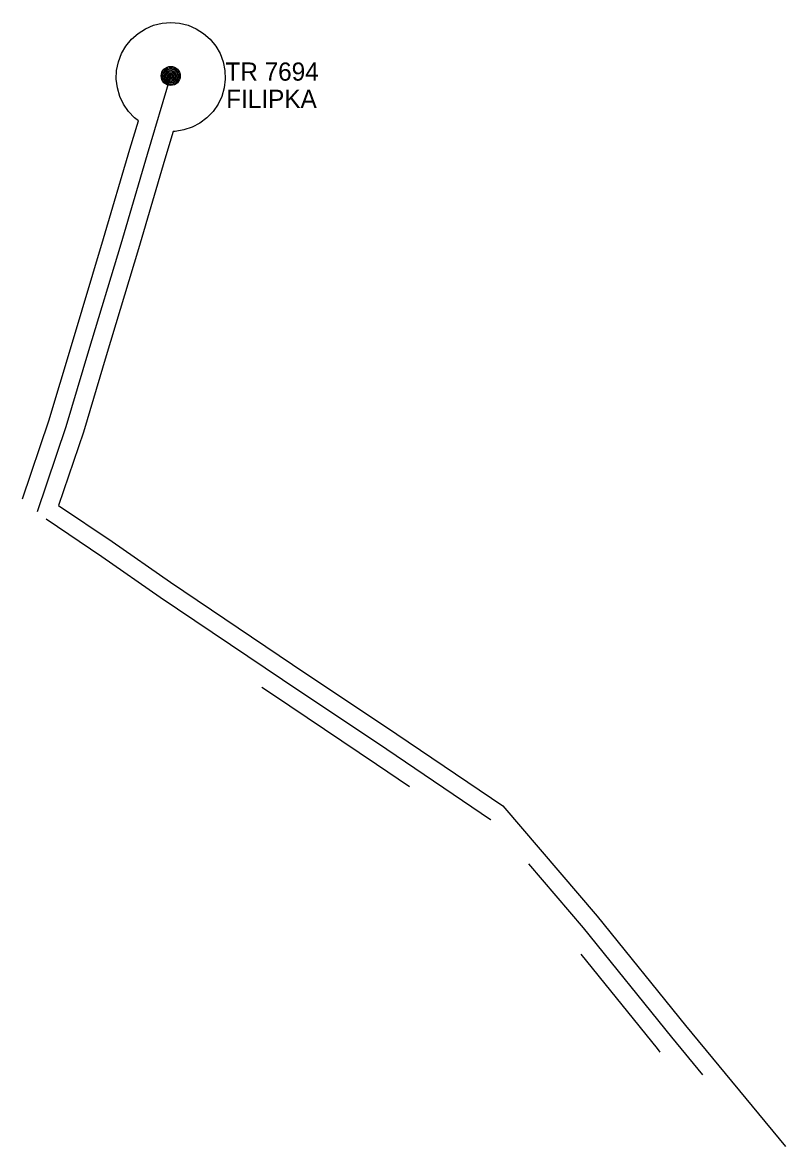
# Model space of a CAD drawing. Extents: x -439095 to -431527, y -1129525 to -1119219.
# Drawn here: x -436127 to -435708, y -1129525 to -1128907 of the extents above; entities that cross this region are included whole.
import ezdxf

# ---------------------------------------------------------------- set-up
doc = ezdxf.new("R2010")
doc.units = 0
for name, color, linetype in [('13861012_venkovní vedení elektrické sítě VN 1-35 kV_Stav', 7, 'Continuous'), ('14801013_OP vedení elektrické sítě_Stav', 7, 'Continuous'), ('Trafostanice', 7, 'Continuous'), ('Vrstva 13', 7, 'Continuous')]:
    doc.layers.add(name, color=color, linetype=linetype)

msp = doc.modelspace()

# ---------------------------------------------------------------- linework, layer by layer
at = {"layer": '13861012_venkovní vedení elektrické sítě VN 1-35 kV_Stav'}
for points in [[(-436118.97, -1129175.73), (-436103.05, -1129129.02), (-436090.64, -1129087.28), (-436072.97, -1129028.48), (-436058.42, -1128979.12), (-436058.42, -1128979.12), (-436045.78, -1128936.61), (-436045.65, -1128936.11)], [(-436114.14, -1129179.87), (-436083.54, -1129200.57), (-436083.54, -1129200.57), (-436051.43, -1129222.83), (-435984.18, -1129268.23), (-435926.85, -1129306.63), (-435869.79, -1129345.24), (-435869.65, -1129345.4)], [(-435848.84, -1129369.7), (-435818.82, -1129404.77), (-435770.25, -1129464.95), (-435753.15, -1129485.66)]]:
    msp.add_lwpolyline(points, dxfattribs=at)
at = {"layer": '14801013_OP vedení elektrické sítě_Stav'}
for points in [[(-436063.39, -1128960.75), (-436065.49, -1128959.18), (-436068.83, -1128955.7), (-436071.58, -1128951.72), (-436073.64, -1128947.36), (-436074.99, -1128942.72), (-436075.57, -1128937.93), (-436075.38, -1128933.11), (-436074.41, -1128928.38), (-436072.7, -1128923.86), (-436070.28, -1128919.68), (-436067.23, -1128915.94), (-436063.62, -1128912.74), (-436059.54, -1128910.16), (-436055.09, -1128908.27), (-436050.41, -1128907.11), (-436045.59, -1128906.72), (-436040.78, -1128907.11), (-436036.09, -1128908.27), (-436031.65, -1128910.16), (-436027.57, -1128912.74), (-436023.96, -1128915.94), (-436020.9, -1128919.68), (-436018.49, -1128923.86), (-436016.78, -1128928.38), (-436015.81, -1128933.11), (-436015.62, -1128937.93), (-436016.2, -1128942.72), (-436017.54, -1128947.36), (-436019.61, -1128951.72), (-436022.36, -1128955.7), (-436025.7, -1128959.18), (-436029.56, -1128962.08), (-436033.84, -1128964.32), (-436038.41, -1128965.85), (-436043.18, -1128966.63), (-436044.27, -1128966.63)], [(-436127.15, -1129168.73), (-436112.58, -1129125.98), (-436100.22, -1129084.42), (-436082.55, -1129025.63), (-436068.07, -1128976.49), (-436068.07, -1128976.48), (-436063.39, -1128960.75)], [(-436044.27, -1128966.63), (-436048.8, -1128981.85), (-436063.38, -1129031.33), (-436081.06, -1129090.14), (-436093.52, -1129132.06), (-436107.28, -1129172.44), (-436077.87, -1129192.33), (-436077.82, -1129192.37), (-436045.78, -1129214.57), (-435978.6, -1129259.93), (-435921.27, -1129298.33), (-435863.07, -1129337.71), (-435862.05, -1129338.9)], [(-435914.32, -1129327.18), (-435932.44, -1129314.92), (-435989.76, -1129276.53), (-435995.57, -1129272.6)], [(-435863.07, -1129337.71), (-435811.12, -1129398.37), (-435762.5, -1129458.63), (-435707.57, -1129525.16)], [(-435776.43, -1129473.17), (-435778, -1129471.27), (-435819.93, -1129419.31)]]:
    msp.add_lwpolyline(points, dxfattribs=at)
at = {"layer": 'Trafostanice'}
for radius in [5.25, 4.55, 3.85, 3.15, 2.45, 1.75, 1.05, 0.35]:
    msp.add_circle((-436045.64, -1128936.14), radius, dxfattribs=at)

# ---------------------------------------------------------------- texts
at = {"layer": 'Vrstva 13'}
for s, p in [('TR 7694', (-436015.54, -1128938.74)), ('FILIPKA', (-436015.12, -1128953.74))]:
    msp.add_text(s, height=10, dxfattribs=at).set_placement(p)

doc.saveas('drawing.dxf')
